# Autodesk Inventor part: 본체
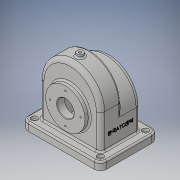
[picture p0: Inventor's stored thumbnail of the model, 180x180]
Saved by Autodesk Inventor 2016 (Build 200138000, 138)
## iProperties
Created: 2017-11
Part Number: 본체
Material: 일반
Document SubType Name: Modeling
Designer: Administrator
Density: 1 g/cm^3
Appearance: 기본값
Author: Administrator
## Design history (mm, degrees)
sketch "스케치2"
  geometry: L1 (55, 75)-(-55, 75); L2 (-55, 75)-(-55, -75); L3 (-55, -75)-(55, -75); L4 (55, -75)-(55, 75); L5 (55, 75)-(-55, -75); L6 (-55, 75)-(55, -75); 1 further point
  constraints: 12 end point, 2 midpoint, 2 parallel, 1 horizontal, 1 perpendicular
  dimensions: "d1" = 110 distance of L2.end L3.end; "d2" = 150 distance of L3.end L1.start
extrude "돌출1" new body sketch "스케치2" distance "d3" = 15; taper "d4" = 0 deg
fillet "모깎기1" dims "d5" = 12
sketch "스케치3"
  geometry: A1 r 12 centre (-43, -63) between (-55, -63) and (-43, -75) reference; A2 r 12 centre (-43, 63) between (-43, 75) and (-55, 63) reference; A3 r 12 centre (43, -63) between (43, -75) and (55, -63) reference; A4 r 12 centre (43, 63) between (55, 63) and (43, 75) reference; 5 further points
  constraints: 4 coincident
hole "구멍1" sketch "스케치3" at (-43, -63), (43, -63), (43, 63), (-43, 63) diameter "d6" = 5; stored, may be unused: countersink angle "d10" = 90 deg, drill point angle "d12" = 118 deg; dims "d7" = 6, "d8" = 12, "d9" = 5, "d11" = 12
fillet "모깎기2" dims "d13" = 3
sketch "스케치6"
  geometry: L1 (38, -58)-(-38, -58); L2 (-38, -58)-(-38, 58); L3 (-38, 58)-(38, 58); L4 (38, 58)-(38, -58); L5 (38, -58)-(-38, 58); L6 (-38, -58)-(38, 58); 1 further point
  constraints: 12 end point, 2 midpoint, 2 parallel, 1 horizontal, 1 perpendicular
  dimensions: "d14" = 116 distance of L1.end L2.end; "d15" = 76 distance of L1.start L1.end
extrude "돌출2" join sketch "스케치6" distance "d16" = 65; taper "d17" = 0 deg
sketch "스케치8"
  geometry: L1 (-5, -15)-(121, -15) reference; L2 (0, 65)-(116, 65) reference; A1 r 58 centre (58, 65) between (116, 65) and (0, 65); 3 further points
  constraints: 2 midpoint, 2 point on circle, 2 point on line, 1 centre point, 1 vertical alignment
  dimensions: "d21" = 116 diameter of A1; "d29" = 0 distance of point (58, 65) A1.centre
extrude "돌출3" join sketch "스케치8" distance "d22" = 38; taper "d23" = 0 deg
sketch "스케치9"
  geometry: L1 (-5, -15)-(121, -15) reference; C1 r 37.5 at (58, 50); 2 further points
  constraints: 1 centre point, 1 midpoint, 1 vertical alignment
  dimensions: "d25" = 75 diameter of C1; "d39" = 65 distance from line of L1 C1.centre
extrude "돌출4" join sketch "스케치9" distance "d26" = 9; taper "d27" = 0 deg
sketch "스케치10"
  geometry: L1 (-17, 42)-(133, 42); L2 (133, 42)-(133, 71.41); L3 (133, 71.41)-(-17, 71.41); L4 (-17, 71.41)-(-17, 42); L5 (-17, 42)-(133, 71.41); L6 (133, 42)-(-17, 71.41); L7 (-5, -15)-(121, -15) reference; L8 (0, 65)-(116, 65) reference; 7 further points
  constraints: 12 end point, 4 midpoint, 2 parallel, 1 horizontal, 1 perpendicular, 1 vertical alignment, 1 other
  dimensions: "d30" = 57 distance between parallel lines of L1 L7; "d31" = 150 distance of L2.end L3.end; "d32" = 29.40983 distance of L1.end L2.end
extrude "돌출5" cut sketch "스케치10" distance "d33" = 38; taper "d34" = 0 deg
sketch "스케치12"
  geometry: L1 (-5, -15)-(121, -15) reference; L2 (116, 42)-(0, 42) reference; A1 r 58 centre (58, 42) between (116, 42) and (0, 42); 2 further points
  constraints: 2 midpoint, 2 point on circle, 2 point on line, 1 centre point, 1 vertical alignment
  dimensions: "d35" = 116 diameter of A1
extrude "돌출6" join sketch "스케치12" distance "d36" = 38; taper "d37" = 0 deg
sketch "스케치13"
  geometry: L1 (-5, -15)-(121, -15) reference; C1 r 31 at (58, 50); 1 further point
  constraints: 1 centre point
  dimensions: "d38" = 62 diameter of C1; "d40" = 65 distance from line of L1 C1.centre
extrude "돌출7" join sketch "스케치13" distance "d41" = 10; taper "d42" = 0 deg
sketch "스케치14"
  geometry: C1 r 16 at (0, 0); C2 r 31 at (0, 0) reference; 1 further point
  constraints: 1 centre point, 1 concentric
  dimensions: "d43" = 32 diameter of C1
extrude "돌출8" cut sketch "스케치14" stored distance "d44" = 10; taper "d45" = 0 deg
node "작업 평면1"
sketch "스케치16"
  geometry: L1 (116, 0)-(116, 65) reference; L2 (0, 0)-(0, 65) reference; L3 (5, 0)-(5, 42); L4 (111, 0)-(111, 42); L5 (5, 0)-(5, -15); L6 (5, -15)-(111, -15); L7 (111, -15)-(111, 0); A1 r 58 centre (58, 42) between (116, 42) and (0, 42) reference; A2 r 53 centre (58, 42) between (111, 42) and (5, 42); 1 further point
  constraints: 10 end point, 2 parallel, 2 perpendicular, 2 point on circle, 1 centre point, 1 midpoint, 1 vertical
  dimensions: "d48" = 5 radial gap between concentric circles of A1 A2; "d49" = 5 distance between parallel lines of L2 L3; "d50" = 5 distance between parallel lines of L1 L4
extrude "돌출9" cut sketch "스케치16" distance "d51" = 38; taper "d52" = 0 deg
sketch "스케치17"
  geometry: 1 further point
sketch "스케치19"
  geometry: L1 (0, 0)-(0, 65) reference; L2 (116, 0)-(116, 65) reference; L3 (5, 0)-(5, 65); L4 (111, 65)-(111, 0); L5 (5, 0)-(5, -15); L6 (5, -15)-(111, -15); L7 (111, -15)-(111, 0); A1 r 58 centre (58, 65) between (116, 65) and (0, 65) reference; A2 r 53 centre (58, 65) between (111, 65) and (5, 65); 2 further points
  constraints: 10 end point, 2 perpendicular, 2 point on circle, 1 centre point, 1 coincident, 1 midpoint, 1 vertical, 2 other
  dimensions: "d56" = 5 radial gap between concentric circles of A1 A2
extrude "돌출11" cut sketch "스케치19" distance "d57" = 28; taper "d58" = 0 deg
sketch "스케치20"
  geometry: L1 (-63, -65)-(63, -65) reference; C1 r 16 at (0, 0) reference; 3 further points
  constraints: 1 midpoint, 1 vertical alignment
  dimensions: "d59" = 29 distance of point (0, 29) C1.centre
hole "구멍2" sketch "스케치20" at (0, 29) diameter "d60" = 3; stored, may be unused: countersink angle "d64" = 90 deg, drill point angle "d66" = 118 deg; dims "d61" = 6, "d62" = 4, "d63" = 2, "d65" = 8
node "작업 평면2"
sketch "스케치21"
  geometry: L1 (-38, 58)-(-38, -58) reference; L2 (0, 58)-(0, -58) reference; C1 r 6 at (-19, 0); 2 further points
  constraints: 1 centre point, 1 horizontal alignment, 1 midpoint
  dimensions: "d71" = 12 diameter of C1; "d72" = 19 distance from line of L2 C1.centre
extrude "돌출12" join sketch "스케치21" distance "d73" = 3; taper "d75" = 0 deg; dims "d74" = 6, "d76" = 0
sketch "스케치24"
  geometry: C1 r 2.5 at (0, 0); C2 r 6 at (0, 0) reference; 1 further point
  constraints: 1 centre point, 1 concentric
  dimensions: "d77" = 5 diameter of C1
hole "구멍3" sketch "스케치24" at (0, 0) diameter "d78" = 5; stored, may be unused: countersink angle "d82" = 90 deg, drill point angle "d84" = 118 deg; dims "d79" = 6, "d80" = 4, "d81" = 2, "d83" = 8
sketch "스케치25"
  geometry: C1 r 16 at (0, 0) reference; 2 further points
  dimensions: "d87" = 26 distance of C1.centre point (0, 26)
hole "구멍4" sketch "스케치25" at (0, 26) diameter "d88" = 3; stored, may be unused: countersink angle "d92" = 90 deg, drill point angle "d94" = 118 deg; dims "d89" = 6, "d90" = 4, "d91" = 2, "d93" = 8
chamfer "모따기1" distance "d98" = 1; stored, may be unused: second distance "d99" = 2, angle "d100" = 45 deg
fillet "모깎기5" dims "d101" = 3
sketch "스케치27"
  geometry: L1 (-35, 23)-(-35, -39) reference; L2 (-40, -57)-(46, -57) reference; 2 further points
  constraints: 1 other
  dimensions: "d102" = 38 distance from line of L1 point (3, -17); "d103" = 40 distance from line of L2 point (3, -17)
feature "엠보싱1" sketch "스케치27" dims "d104" = 0.5, "d105" = 0
fillet "모깎기6" dims "d106" = 8
fillet "모깎기7" dims "d107" = 8
fillet "모깎기8" dims "d108" = 3
fillet "모깎기9" dims "d109" = 3
fillet "모깎기10" dims "d110" = 3
fillet "모깎기11" dims "d111" = 3
node "솔리드1"
pattern_circular "원형 패턴1" dims angle "d68" = 360 deg
pattern_circular "원형 패턴2" dims angle "d96" = 360 deg
other parameters: "d47" = -5
